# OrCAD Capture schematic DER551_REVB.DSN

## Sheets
1 PAGE1: size Custom; title: DER-551_Inno3X_54W_Dual_USBPD_5V3A_9V3A; rev: B
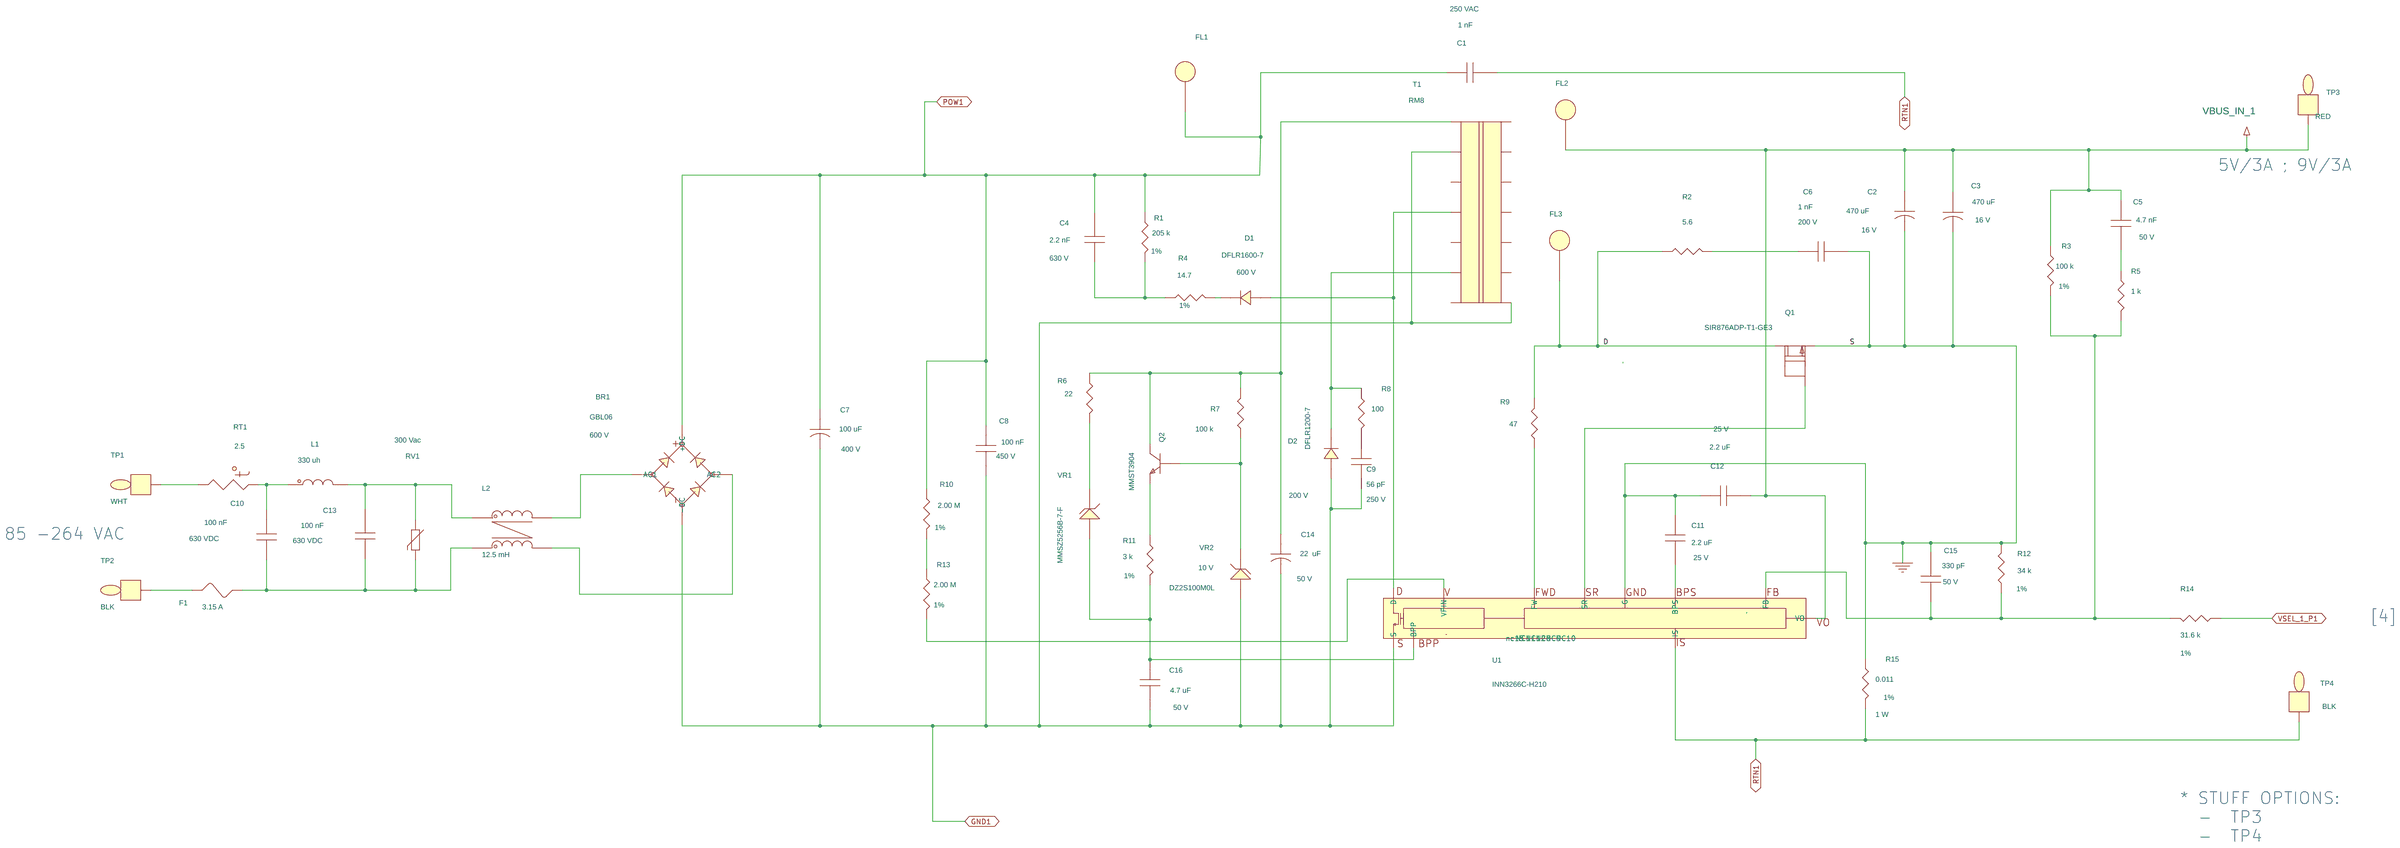
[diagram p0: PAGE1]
2 PAGE2: size Custom
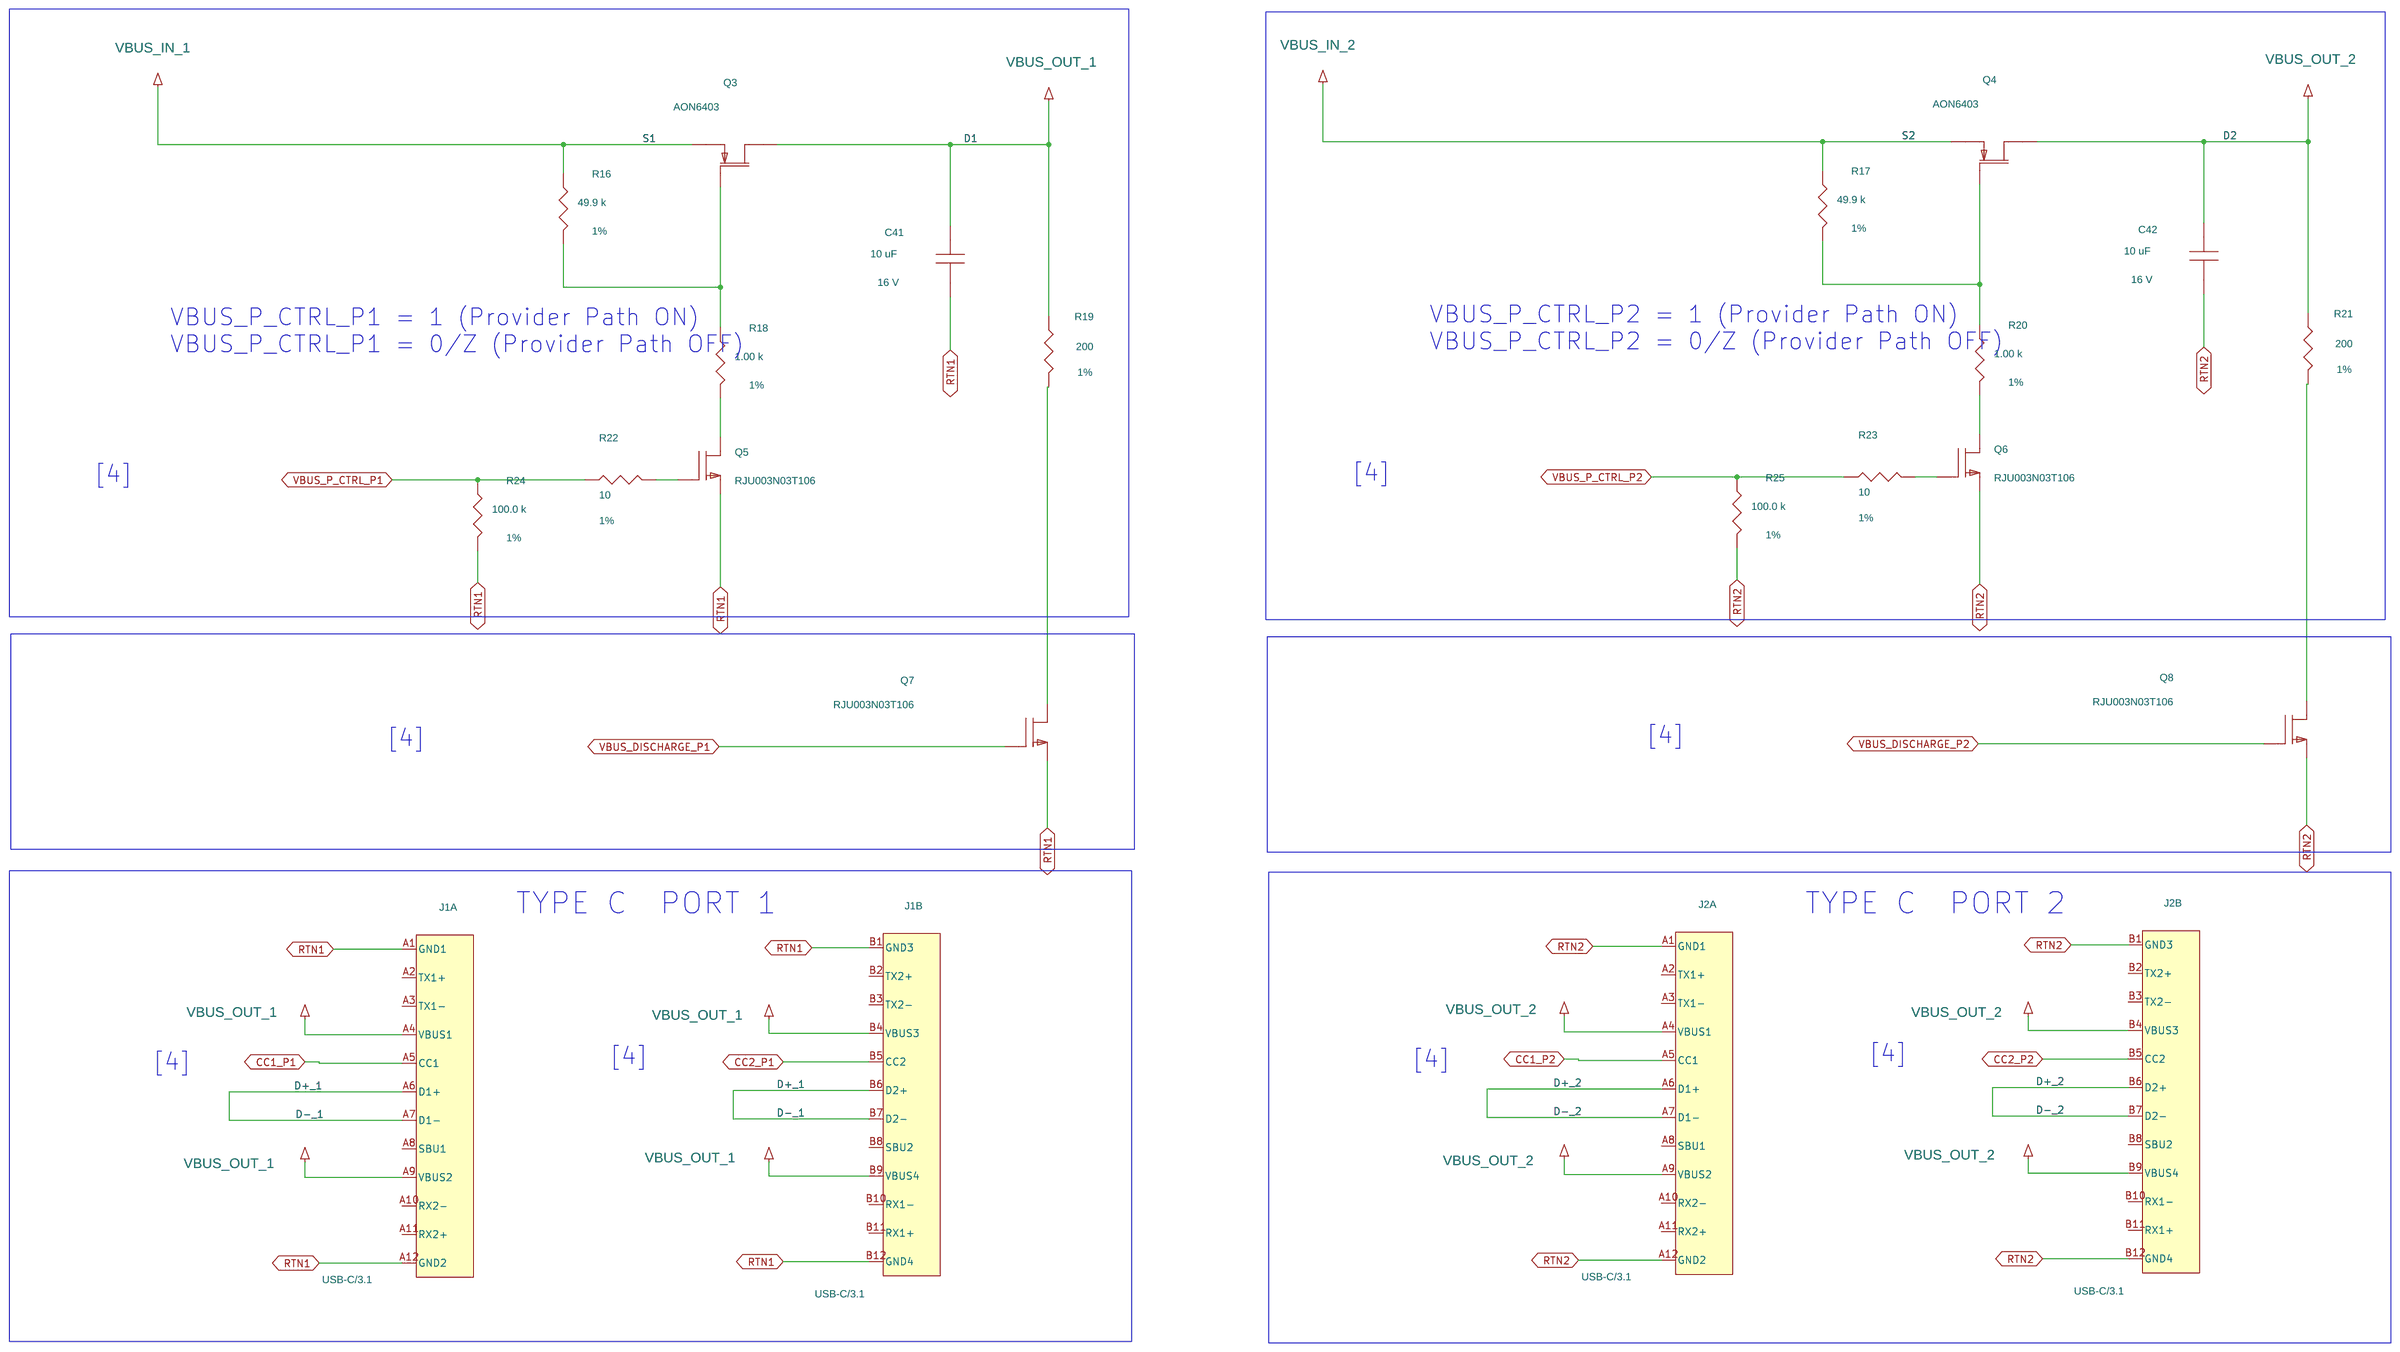
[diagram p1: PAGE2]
3 PAGE3: size Custom
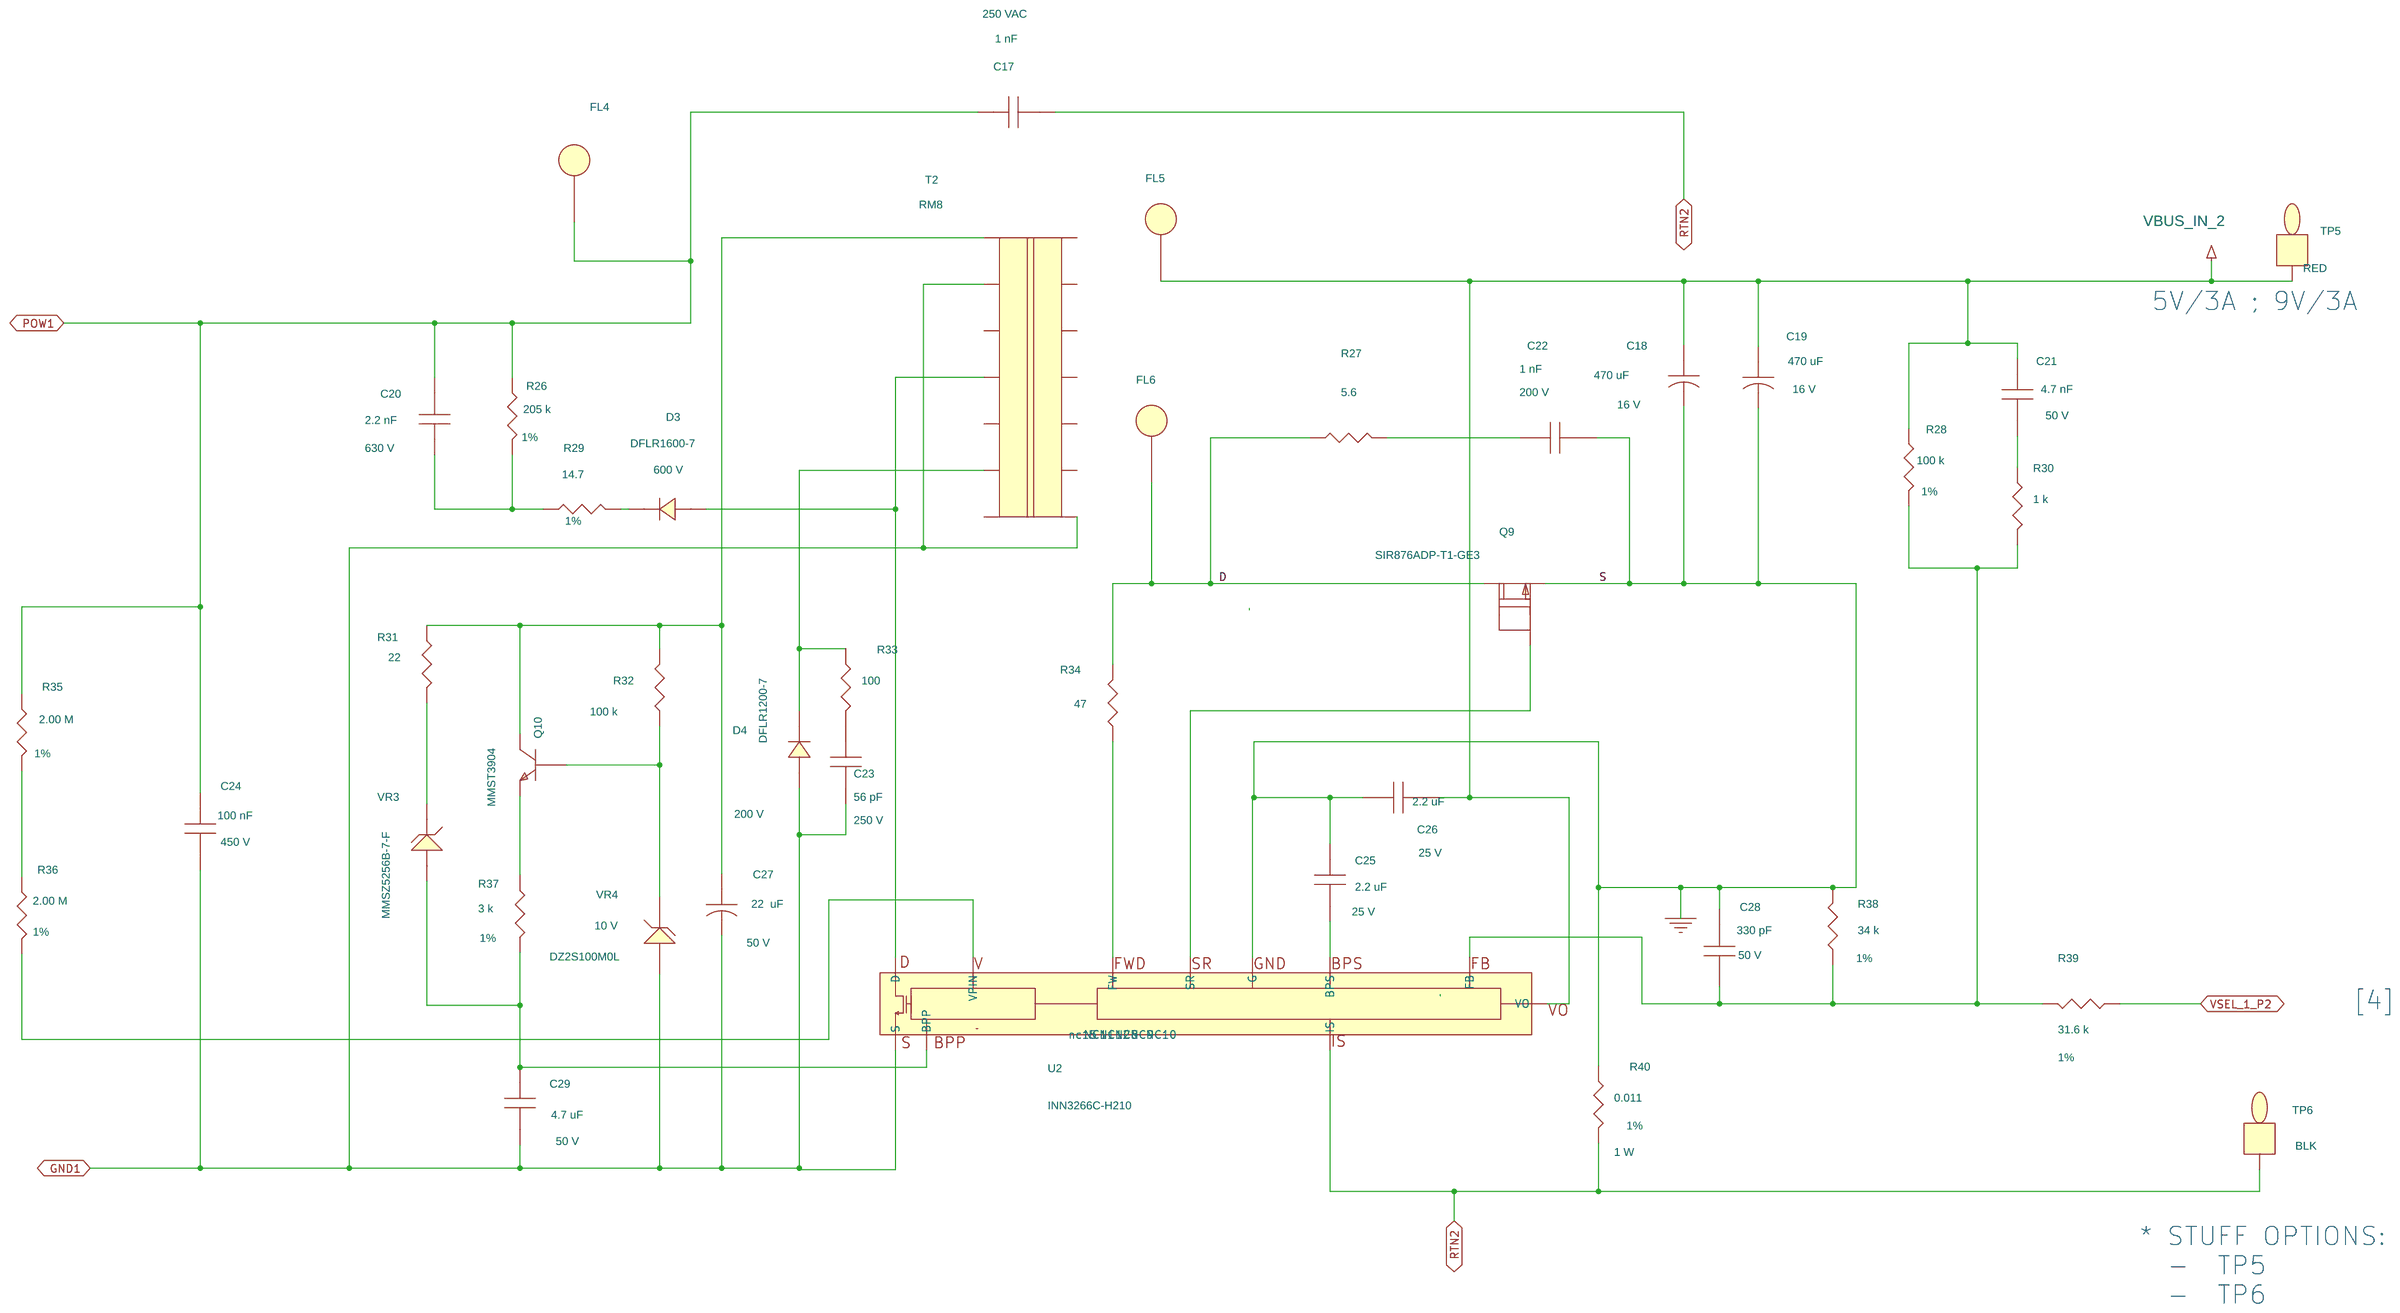
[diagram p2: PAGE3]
4 PAGE4: size Custom
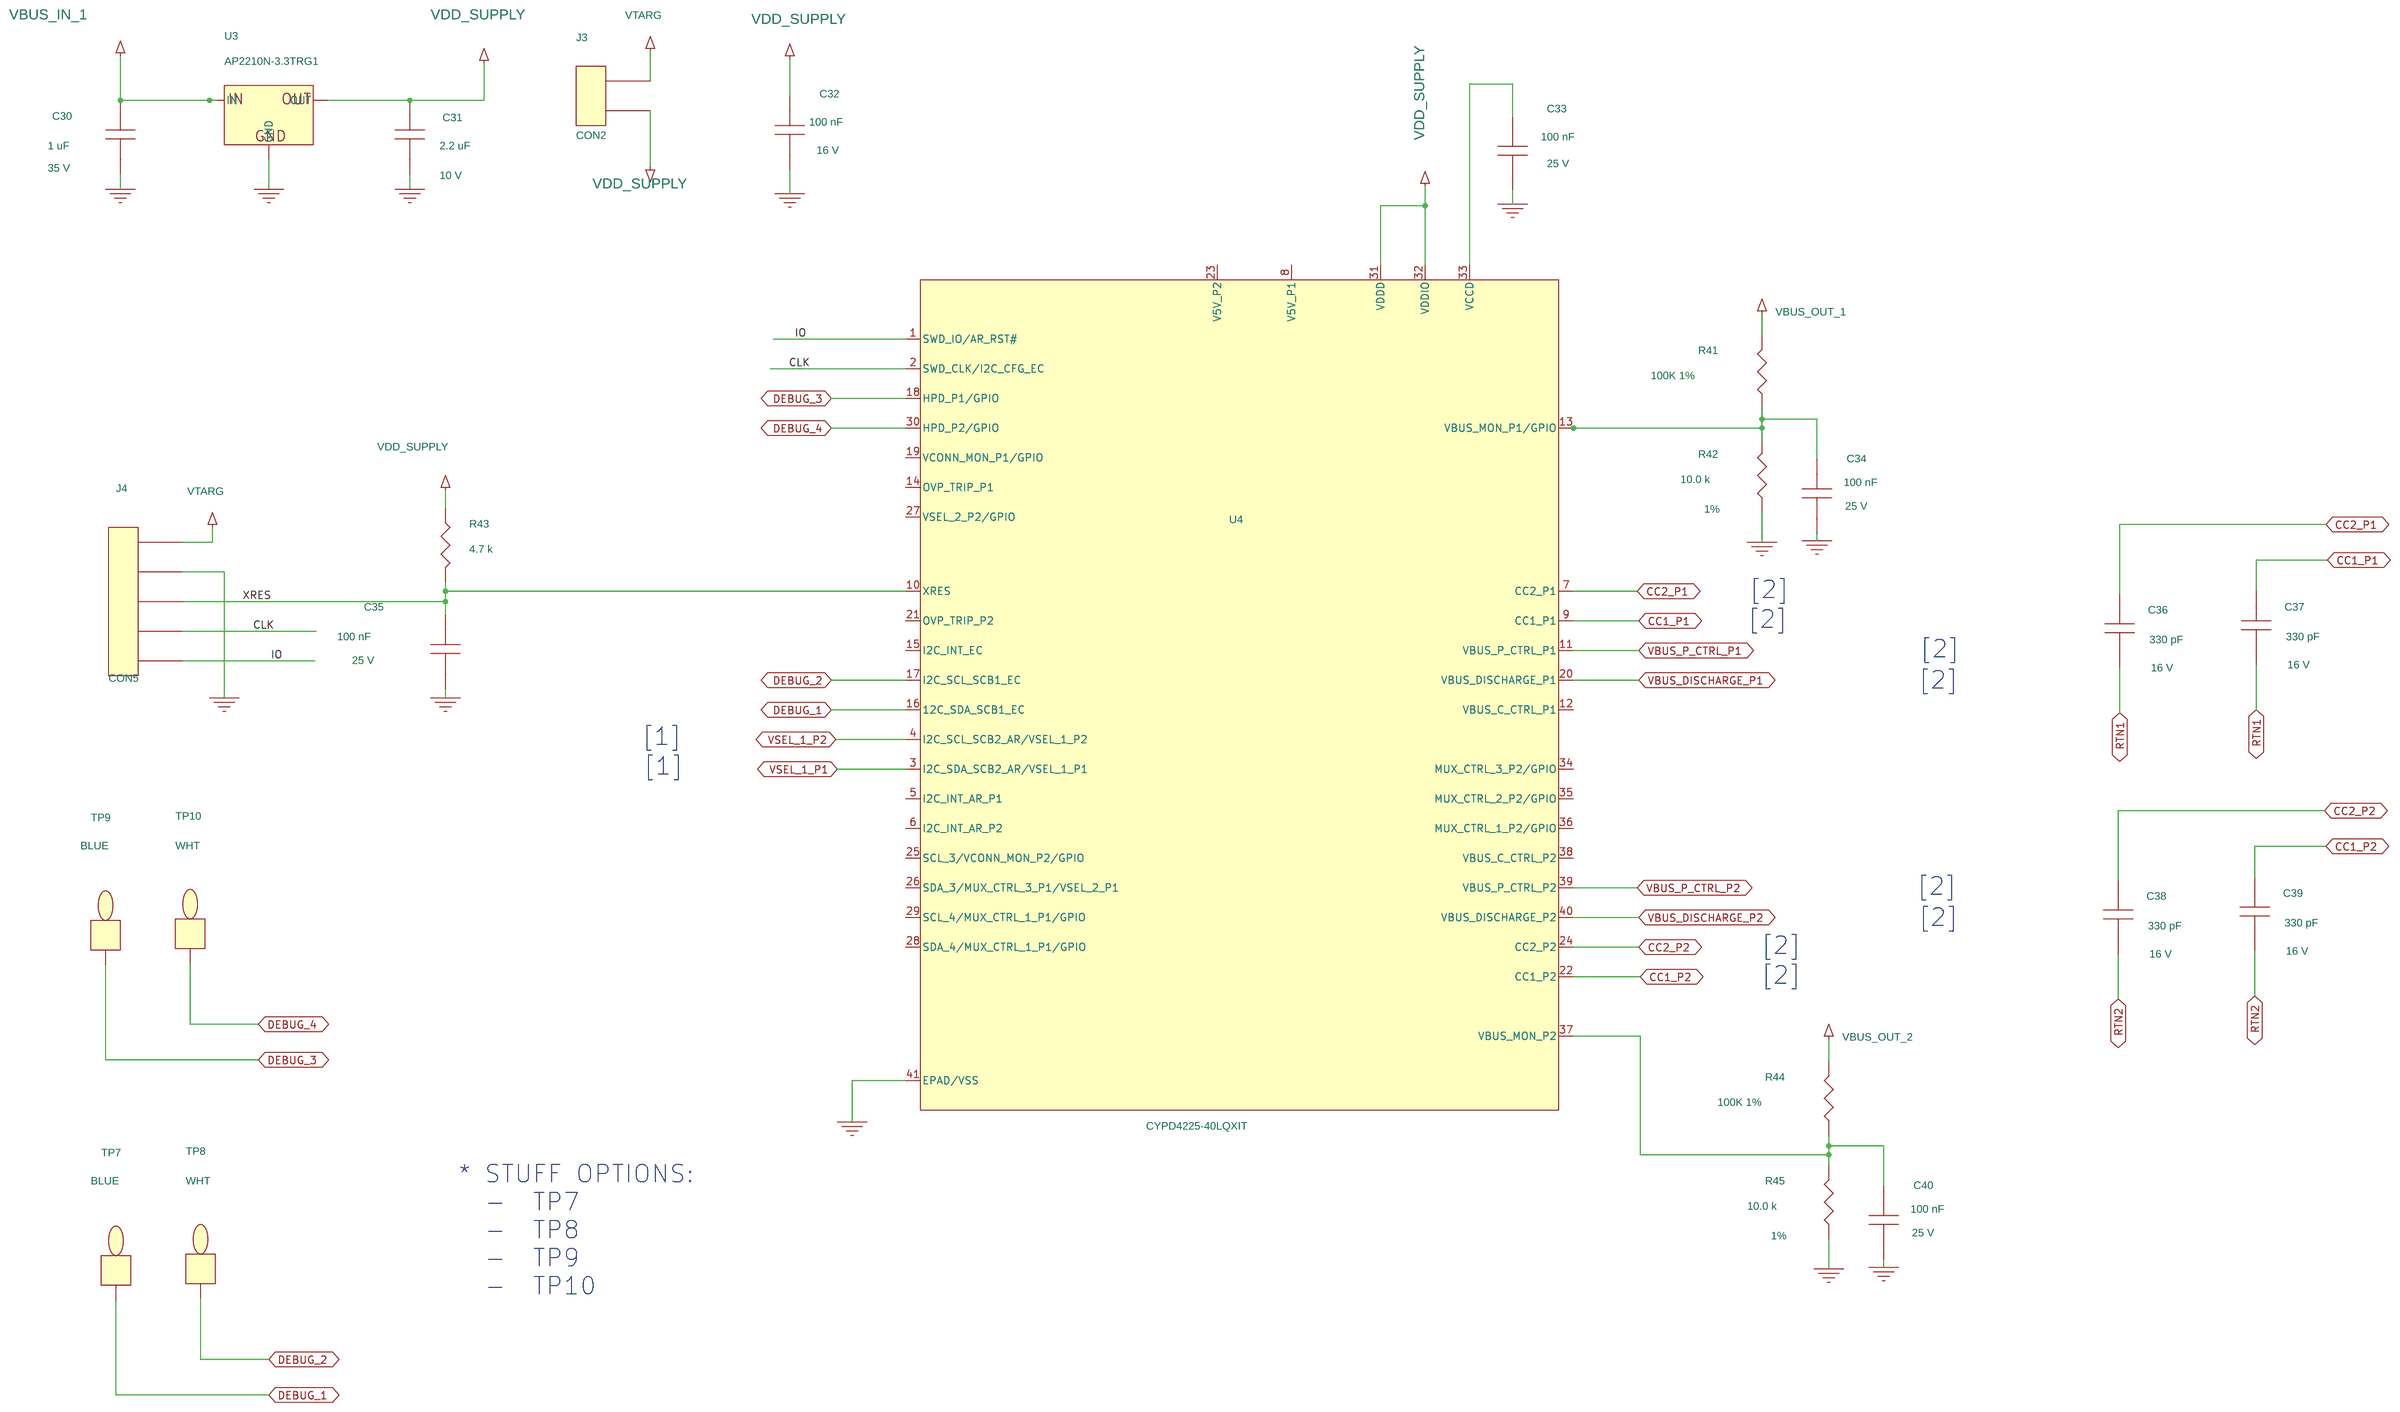
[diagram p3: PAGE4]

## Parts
sheet PAGE1
BR1  GBL06  [pidaxbridgegbl06]
C1  1 nF  [pinpycaprad540x290ls400040]
C2  470 uF  [pipolcapclyd320ls140030]
C3  470 uF  [pipolcapclyd320ls140030]
C4  2.2 nF  [pismc1206]
C5  4.7 nF  [pismc0603]
C6  1 nF  [pismc0805]
C7  100 uF  [pipolcapclyd630ls300040]
C8  100 nF  [pi_np_xcap_rad512x197x395d040]
C9  56 pF  [pismc0603]
C10  100 nF  [pi_np_cap492x236ls394d040]
C11  2.2 uF  [pismc0805]
C12  2.2 uF  [pismc0805]
C13  100 nF  [pi_np_cap492x236ls394d040]
C14  22  uF  [pipolcapclyd200ls80030]
C15  330 pF  [pismc0603]
C16  4.7 uF  [pismc0805]
D1  DFLR1600-7  [pismddflr120012]
D2  DFLR1200-7  [pismddflr120012]
F1  3.15 A  [pi_rst_microfuse]
FL1  Hole_30mils  [pi_hole_30mil]
FL2  Hole_70mils  [pi_hole_70mil]
FL3  Hole_70mils  [pi_hole_70mil]
L1  330 uh  [pi_choke_RL5480-4_d2]
L2  12.5 mH  [PI_TOROID_CMC23X10P7_4P_V]
Q1  SIR876ADP-T1-GE3  [pismpqfn5x6b]
Q2  MMST3904  [pismsot323132]
R1  205 k  [pismr1206]
R2  5.6  [pismr0805]
R3  100 k  [pismr0603]
R4  14.7  [pismr1206]
R5  1 k  [pismr0603]
R6  22  [pismr0603]
R7  100 k  [pismr0603]
R8  100  [pismr0603]
R9  47  [pismr0603]
R10  2.00 M  [pismr1206]
R11  3 k  [pismr0603]
R12  34 k  [pismr0603]
R13  2.00 M  [pismr1206]
R14  31.6 k  [pismr1206]
R15  0.011  [pismr1206]
RT1  2.5  [pi_rad180x395ls235d031]
RV1  300 Vac  [pidisc350x225ls240x140040]
T1  RM8  [pi_bobbin_rm8_12p_clp]
TP1  WHT  [pitpkeystone125x125]
TP2  BLK  [pitpkeystone125x125]
TP3  RED  [pitpkeystone100x100]
TP4  BLK  [pitpkeystone100x100]
U1  INN3266C-H210  [pi_ic_insop_24d]
VR1  MMSZ5256B-7-F  [pi_sm_sod-123_12]
VR2  DZ2S100M0L  [pi_sm_d_ssmini2p]
sheet PAGE2
C41  10 uF  [pismc0805]
C42  10 uF  [pismc0805]
J1  USB-C/3.1  [pi_conn_usb_3p1_top]  (sections A,B)
J2  USB-C/3.1  [pi_conn_usb_3p1_top]  (sections A,B)
Q3  AON6403  [pi_DFN5X6_8L_EP1_P]
Q4  AON6403  [pi_DFN5X6_8L_EP1_P]
Q5  RJU003N03T106  [pismsot323]
Q6  RJU003N03T106  [pismsot323]
Q7  RJU003N03T106  [pismsot323]
Q8  RJU003N03T106  [pismsot323]
R16  49.9 k  [pismr0402]
R17  49.9 k  [pismr0402]
R18  1.00 k  [pismr0805]
R19  200  [pismr1206]
R20  1.00 k  [pismr0805]
R21  200  [pismr1206]
R22  10  [pismr0402]
R23  10  [pismr0402]
R24  100.0 k  [pismr0402]
R25  100.0 k  [pismr0402]
sheet PAGE3
C17  1 nF  [pinpycaprad540x290ls400040]
C18  470 uF  [pipolcapclyd320ls140030]
C19  470 uF  [pipolcapclyd320ls140030]
C20  2.2 nF  [pismc1206]
C21  4.7 nF  [pismc0603]
C22  1 nF  [pismc0805]
C23  56 pF  [pismc0603]
C24  100 nF  [pi_np_xcap_rad512x197x395d040]
C25  2.2 uF  [pismc0805]
C26  2.2 uF  [pismc0805]
C27  22  uF  [pipolcapclyd200ls80030]
C28  330 pF  [pismc0603]
C29  4.7 uF  [pismc0805]
D3  DFLR1600-7  [pismddflr120012]
D4  DFLR1200-7  [pismddflr120012]
FL4  Hole_30mils  [pi_hole_30mil]
FL5  Hole_70mils  [pi_hole_70mil]
FL6  Hole_70mils  [pi_hole_70mil]
Q9  SIR876ADP-T1-GE3  [pismpqfn5x6b]
Q10  MMST3904  [pismsot323132]
R26  205 k  [pismr1206]
R27  5.6  [pismr0805]
R28  100 k  [pismr0603]
R29  14.7  [pismr1206]
R30  1 k  [pismr0603]
R31  22  [pismr0603]
R32  100 k  [pismr0603]
R33  100  [pismr0603]
R34  47  [pismr0603]
R35  2.00 M  [pismr1206]
R36  2.00 M  [pismr1206]
R37  3 k  [pismr0603]
R38  34 k  [pismr0603]
R39  31.6 k  [pismr1206]
R40  0.011  [pismr1206]
T2  RM8  [pi_bobbin_rm8_12p_clp]
TP5  RED  [pitpkeystone100x100]
TP6  BLK  [pitpkeystone100x100]
U2  INN3266C-H210  [pi_ic_insop_24d]
VR3  MMSZ5256B-7-F  [pi_sm_sod-123_12]
VR4  DZ2S100M0L  [pi_sm_d_ssmini2p]
sheet PAGE4
C30  1 uF  [pismc0603]
C31  2.2 uF  [pismc0603]
C32  100 nF  [pismr0402]
C33  100 nF  [pismc0603]
C34  100 nF  [pismc0603]
C35  100 nF  [pismc0603]
C36  330 pF  [pismr0402]
C37  330 pF  [pismr0402]
C38  330 pF  [pismr0402]
C39  330 pF  [pismr0402]
C40  100 nF  [pismc0603]
J3  CON2  [pimolex2kkheader]
J4  CON5  [pi_molex_5p_100_header_ra]
R41  100K 1%  [pismr0402]
R42  10.0 k  [pismr0402]
R43  4.7 k  [pismr0402]
R44  100K 1%  [pismr0402]
R45  10.0 k  [pismr0402]
TP7  BLUE  [pitpkeystone100x100]
TP8  WHT  [pitpkeystone100x100]
TP9  BLUE  [pitpkeystone100x100]
TP10  WHT  [pitpkeystone100x100]
U3  AP2210N-3.3TRG1  [pismsot23132]
U4  CYPD4225-40LQXIT  [qfn50p600x600x60-41t470x470n]

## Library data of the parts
BR1 = DISCRETE_BRIDGE_+~~-: Disp_Voltage: 600 V; Part Number: 15-01112-00
C1 C17 = CAP_NP: ALT_SYMBOLS: pinpycaprad540x290ls400040h,pinpycaprad500x220ls400040; Disp_Voltage: 250 VAC; FPLIST: pinpycaprad540x290ls400040,pinpycaprad540x290ls400040h,pinpycaprad500x220ls400040; Part Number: 20-00375-00; Voltage: 250 VAC
C2 C3 C18 C19 = CAP_POL: ALT_SYMBOLS: pipolcapclyd320ls140030430h; Disp_Voltage: 16 V; FPLIST: pipolcapclyd320ls140030,pipolcapclyd320ls140030430h; Part Number: 20-08681-00; Voltage: 16 V
C4 C20 = CAP_NP: Disp_Voltage: 630 V; Part Number: 20-08609-00; Voltage: 630 V
C5 C21 = CAP_NP: Disp_Voltage: 50 V; Part Number: 20-08578-00; Voltage: 50 V
C6 C22 = CAP_NP: Disp_Voltage: 200 V; PCB Editor PCBFP: pismc0603; Part Number: 20-00737-00; Voltage: 200 V
C7 = CAP_POL: ALT_SYMBOLS: pipolcapclyd630ls3000401120h; Disp_Voltage: 400 V; FPLIST: pipolcapclyd630ls300040,pipolcapclyd630ls3000401120h; Part Number: 20-00517-00; Voltage: 400 V
C8 C24 = CAP_NP: Disp_Voltage: 450 V; Part Number: 20-01140-00; Voltage: 450 V
C9 C23 = CAP_NP: Disp_Voltage: 250 V; Part Number: 20-01325-00; Voltage: 250 V
C10 C13 = CAP_NP: Disp_Voltage: 630 VDC; Part Number: 20-02095-00; Voltage: 630 VDC
C11 C12 C25 C26 = CAP_NP: Disp_Voltage: 25 V; Part Number: 20-08603-00; Voltage: 25 V
C14 C27 = CAP_POL: ALT_SYMBOLS: pipolcapclyd200ls80030h; Disp_Voltage: 50 V; FPLIST: pipolcapclyd200ls80030,pipolcapclyd200ls80030h; Part Number: 20-00950-00; Voltage: 50 V
C15 C28 = CAP_NP: Disp_Voltage: 50 V; Part Number: 20-08676-00; Voltage: 50 V
C16 C29 = CAP_NP: Disp_Voltage: 50 V; Part Number: 20-01130-00; Voltage: 50 V
D1 D3 = DIODE: Disp_Voltage: 600 V; Part Number: 15-00826-00
D2 D4 = DIODE: COMPGROUP: 1; Disp_Voltage: 200 V; Part Number: 15-01019-00
F1 = FUSE: ALT_SYMBOLS: pirstmicrofusehoz; FPLIST: pi_rst_microfuse,pirstmicrofusehoz; Part Number: 40-00020-00
FL1 FL4 = FlyingLead: Part Number: 35-00284-00
FL2 FL3 FL5 FL6 = FlyingLead: Part Number: 35-00282-00
L1 = INDUCTOR_DOT2: ALT_SYMBOLS: pi_choke_RL5480-4H_d2; FPLIST: pi_choke_RL5480-4_d2,pi_choke_RL5480-4H_d2; Part Number: 30-00334-00
L2 = TORRID_4P_14_23: Part Number: 30-00465-00
Q1 Q9 = FET_N_SGD_123_4_5678: Part Number: 50-00152-00
Q2 Q10 = NPN_BEC: Part Number: 55-00016-00
R1 R26 = R: Disp_Tol: 1%; Part Number: 05-00415-00
R2 R27 = R: Part Number: 05-01465-00
R3 R28 = R: Disp_Tol: 1%; Part Number: 05-01174-00
R4 R29 = R: Disp_Tol: 1%; Part Number: 05-00017-00
R5 R30 = R: Part Number: 05-01688-00
R6 R31 = R: Part Number: 05-01648-00
R7 R32 = R: Part Number: 05-01736-00
R8 R33 = R: Part Number: 05-01664-00
R9 R34 = R: Part Number: 05-01656-00
R10 R13 R35 R36 = R: COMPGROUP: 1; Disp_Tol: 1%; Part Number: 05-03156-00
R11 R37 = R: Disp_Tol: 1%; Part Number: 05-06313-00
R12 R38 = R: Disp_Tol: 1%; Part Number: 05-03235-00
R14 R39 = R: Disp_Tol: 1%; Part Number: 05-00337-00
R15 R40 = R: Disp_Power: 1 W; Disp_Tol: 1%; Part Number: 05-06466-00
RT1 = THERMISTOR: ALT_SYMBOLS: pirad550x410ls300040_h; FPLIST: pi_rad180x395ls235d031,pirad550x410ls300040_h; Part Number: 90-00038-00
RV1 = VARISTOR: Part Number: 85-00031-00
T1 T2 = BRM8_12P_CLP: FPLIST: pi_bobbin_rm8_12p_enertronic,pi_bobbin_rm8_12p_clp; Part Number: 25-01084-00
TP1 = TESTPOINT: Part Number: 35-00044-00
TP2 = TESTPOINT: Part Number: 35-00042-00
TP3 TP5 = TESTPOINT: Part Number: 35-00080-00
TP4 TP6 = TESTPOINT: Part Number: 35-00079-00
U1 U2 = Inno3CP: Part Number: 10-01040-04
VR1 VR3 = DIODE_ZENER: Part Number: 15-01096-00
VR2 VR4 = DIODE_ZENER: Disp_Voltage: 10 V; Part Number: 15-00926-00
C41 C42 = CAP_NP: Disp_Voltage: 16 V; Part Number: 20-00676-00; Voltage: 16 V
J1 J2 = CON24_USB: ALT_SYMBOLS: pi_conn_usb_3p1_topD; FPLIST: pi_conn_usb_3p1_top,pi_conn_usb_3p1_topD; Part Number: 35-00354-00
Q3 Q4 = FET_P_SSSGDDDD: Part Number: 50-00209-00
Q5-Q8 = FET_N_SGD: Part Number: 50-00177-00
R16 R17 = R: Disp_Tol: 1%; Part Number: 05-06006-00
R18 R20 = R: Disp_Tol: 1%; Part Number: 05-03310-00
R19 R21 = R: Disp_Tol: 1%; Part Number: 05-00126-00
R22 R23 = R: Disp_Tol: 1%; Part Number: 05-05596-00
R24 R25 = R: Disp_Tol: 1%; Part Number: 05-06039-00
C30 = CAP_NP: Disp_Voltage: 35 V; Part Number: 20-01134-00; Voltage: 35 V
C31 = CAP_NP: Disp_Voltage: 10 V; Part Number: 20-08740-00; Voltage: 10V
C32 = CAP_NP: Disp_Voltage: 16 V; Part Number: 20-08759-00; Voltage: 16 V
C33-C35 C40 = CAP_NP: Disp_Voltage: 25 V; Part Number: 20-01050-00; Voltage: 25 V
C36-C39 = CAP_NP: Disp_Voltage: 16 V; Part Number: 20-08910-00; Voltage: 16 V
J3 = CON2: Part Number: 35-00078-00
J4 = CON5: Part Number: 35-00312-00
R41 R44 = R: RES SMD 100K OHM 1% 1/10W 0402; DIGI-KEY PART NO: P100KLCT-ND; Disp_Tol: 1%; MFG Part number: ERJ-2RKF1003X; Manufacturer: Panasonic Electronic Components; Part Number: 05-06039-00; Price: 0.1
R42 R45 = R: RES SMD 10K OHM 1% 1/10W 0402; DIGI-KEY PART NO: P10.0KLCT-ND; Disp_Tol: 1%; MFG Part number: ERJ-2RKF1002X; Manufacturer: Panasonic Electronic Components; Part Number: 05-05935-00; Price: 0.1
R43 = R: Part Number: 05-06228-00
TP7 TP9 = TESTPOINT: Part Number: 35-00397-00
TP8 TP10 = TESTPOINT: Part Number: 35-00081-00
U3 = AP2210N: Part Number: 45-00352-00
U4 = CYPD4225: Part Number: 45-00451-00

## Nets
GND: C2.2 C3.2 C6.2 C11.1 C12.1 C15.2 C18.2 C19.2 C22.2 C25.1 C26.1 C28.2 C30.2 C31.2 C32.2 C33.2 C34.2 C35.2 C40.2 J4.2 Q1.1(S) Q9.1(S) R12.1 R15.1 R38.1 R40.1 R42.2 R45.2 U1.2(G) U2.2(G) U3.1(GND) U4.41(EPAD/VSS)
GND1: BR1.4(-DC) C7.2 C8.2 C9.2 C14.2 C16.2 C23.2 C24.2 C27.2 C29.2 D2.2 D4.2 T1.2 T1.CLP2 T2.2 T2.CLP2 U1.16(S) U2.16(S) VR2.2 VR4.2
VBUS_DISCHARGE_P1: Q7.2(G) U4.20(VBUS_DISCHARGE_P1)
VBUS_DISCHARGE_P2: Q8.2(G) U4.40(VBUS_DISCHARGE_P2)
VBUS_IN_1: C2.1 C3.1 C5.1 C12.2 C30.1 FL2.1 Q3.1(S1) R3.1 R16.1 TP3.1 U1.6(VO) U3.3(IN)
VBUS_IN_2: C18.1 C19.1 C21.1 C26.2 FL5.1 Q4.1(S1) R17.1 R28.1 TP5.1 U2.6(VO)
VBUS_OUT_1: C41.1 J1.A4(VBUS1) J1.A9(VBUS2) J1.B4(VBUS3) J1.B9(VBUS4) Q3.7(D7) R19.1 R41.1
VBUS_OUT_2: C42.1 J2.A4(VBUS1) J2.A9(VBUS2) J2.B4(VBUS3) J2.B9(VBUS4) Q4.7(D7) R21.1 R44.1
VBUS_P_CTRL_P1: R22.1 R24.1 U4.11(VBUS_P_CTRL_P1)
VBUS_P_CTRL_P2: R23.1 R25.1 U4.39(VBUS_P_CTRL_P2)
VDD_SUPPLY: C31.1 C32.1 J3.1 R43.1 U3.2(OUT) U4.31(VDDD) U4.32(VDDIO)
CC1_P1: C37.1 J1.A5(CC1) U4.9(CC1_P1)
CC1_P2: C39.1 J2.A5(CC1) U4.22(CC1_P2)
CC2_P1: C36.1 J1.B5(CC2) U4.7(CC2_P1)
CC2_P2: C38.1 J2.B5(CC2) U4.24(CC2_P2)
CLK: J4.4 U4.2(SWD_CLK/I2C_CFG_EC)
D: FL3.1 Q1.5(D) R2.2 R9.1
D (page PAGE3): FL6.1 Q9.5(D) R27.2 R34.1
D+_1: J1.A6(D1+) J1.A7(D1-) J1.B6(D2+) J1.B7(D2-)
D+_2: J2.A6(D1+) J2.A7(D1-) J2.B6(D2+) J2.B7(D2-)
DEBUG_1: TP7.1 U4.16(12C_SDA_SCB1_EC)
DEBUG_2: TP8.1 U4.17(I2C_SCL_SCB1_EC)
DEBUG_3: TP9.1 U4.18(HPD_P1/GPIO)
DEBUG_4: TP10.1 U4.30(HPD_P2/GPIO)
IO: J4.5 U4.1(SWD_IO/AR_RST#)
NC8: U1.8(NC8) U2.8(NC8)
NC9: U1.9(NC9) U2.9(NC9)
NC10: U1.10(NC10) U2.10(NC10)
NC11: U1.11(NC11) U2.11(NC11)
NC12: U1.12(NC12) U2.12(NC12)
NC15: U1.15(nc15) U2.15(nc15)
POW1: BR1.1(+DC) C1.1 C4.2 C7.1 C8.1 C17.1 C20.2 C24.1 FL1.1 FL4.1 R1.2 R10.2 R26.2 R35.2
RTN1: C1.2 C36.2 C37.2 C41.2 J1.A1(GND1) J1.A12(GND2) J1.B1(GND3) J1.B12(GND4) Q5.1(S) Q7.1(S) R15.2 R24.2 TP4.1 U1.1(IS)
RTN2: C17.2 C38.2 C39.2 C42.2 J2.A1(GND1) J2.A12(GND2) J2.B1(GND3) J2.B12(GND4) Q6.1(S) Q8.1(S) R25.2 R40.2 TP6.1 U2.1(IS)
VSEL_1_P1: R14.1 U4.3(I2C_SDA_SCB2_AR/VSEL_1_P1)
VSEL_1_P2: R39.1 U4.4(I2C_SCL_SCB2_AR/VSEL_1_P2)
VTARG: J3.2 J4.1
XRES: C35.1 J4.3 R43.2 U4.10(XRES)
N2239928: D1.2 T1.10 U1.24(D)
N2254675: C4.1 R1.1 R4.2
N2276765: C16.1 R11.2 U1.14(BPP) VR1.2
N2494768: C14.1 Q2.3(COLLECTOR) R6.1 R7.1 T1.1
N2642535: Q2.2(EMITTER) R11.1
N2666518: R9.2 U1.7(FW)
N2722737: C6.1 R2.1
N2725054: D2.1 R8.1 T1.12
N2729570: Q1.4(G) U1.5(SR)
N2736973: C15.1 R3.2 R5.2 R12.2 R14.2 U1.3(FB)
N2741729: D1.1 R4.1
N2742169: Q2.1(BASE) R7.2 VR2.1
N2993205: R6.2 VR1.1
N2996861: C5.2 R5.1
N4181205: R10.1 R13.2
N4181233: R13.1 U1.13(VPIN)
N11315036: Q4.4(G) R17.2 R20.1
N11315198: Q6.3(D) R20.2
N11315244: Q8.3(D) R21.2
N11315300: Q6.2(G) R23.2
N11318075: Q3.4(G) R16.2 R18.1
N11318137: Q7.3(D) R19.2
N11318145: Q5.3(D) R18.2
N11318201: Q5.2(G) R22.2
N11323189: C27.1 Q10.3(COLLECTOR) R31.1 R32.1 T2.1
N11323399: D3.2 T2.10 U2.24(D)
N11323505: C22.1 R27.1
N11323517: C21.2 R30.1
N11323551: C20.1 R26.1 R29.2
N11323577: D4.1 R33.1 T2.12
N11323649: D3.1 R29.1
N11323661: C28.1 R28.2 R30.2 R38.2 R39.2 U2.3(FB)
N11323821: Q9.4(G) U2.5(SR)
N11323873: R31.2 VR3.1
N11323885: Q10.1(BASE) R32.2 VR4.1
N11323925: R34.2 U2.7(FW)
N11323959: Q10.2(EMITTER) R37.1
N11324073: C29.1 R37.2 U2.14(BPP) VR3.2
N11324349: R36.1 U2.13(VPIN)
N11338172: R35.1 R36.2
N11773410: F1.2 TP2.1
N11773414: RT1.1 TP1.1
N11773458: C10.1 C13.1 F1.1 L2.1 RV1.2
N11773490: C13.2 L1.1 L2.2 RV1.1
N11773520: BR1.3(AC2) L2.4
N11773524: BR1.2(AC1) L2.3
N11791704: C34.1 R41.2 R42.1 U4.13(VBUS_MON_P1/GPIO)
N11792407: C40.1 R44.2 R45.1 U4.37(VBUS_MON_P2)
N11794782: C33.1 U4.33(VCCD)
N11800517: C10.2 L1.2 RT1.2
N11809700: C11.2 U1.4(BPS)
N11811366: C25.2 U2.4(BPS)
N11812707: C23.1 R33.2
N11857827: C9.1 R8.2

Not connected (* = marked no-connect by the designer): J1 A2(TX1+) A3(TX1-) A8(SBU1) A10(RX2-) A11(RX2+) B2(TX2+) B3(TX2-) B8(SBU2) B10(RX1-) B11(RX1+); J2 A2(TX1+) A3(TX1-) A8(SBU1) A10(RX2-) A11(RX2+) B2(TX2+) B3(TX2-) B8(SBU2) B10(RX1-) B11(RX1+); Q1 2(S2) 3(S3) 6(D6) 7(D7) 8(D8); Q9 2(S2) 3(S3) 6(D6) 7(D7) 8(D8); T1 3 4 5 6 7 8 9 11 CLP1; T2 3 4 5 6 7 8 9 11 CLP1; U4 5(I2C_INT_AR_P1) 6(I2C_INT_AR_P2) 8(V5V_P1) 12(VBUS_C_CTRL_P1) 14(OVP_TRIP_P1) 15(I2C_INT_EC) 19(VCONN_MON_P1/GPIO) 21(OVP_TRIP_P2) 23(V5V_P2) 25(SCL_3/VCONN_MON_P2/GPIO) 26(SDA_3/MUX_CTRL_3_P1/VSEL_2_P1) 27(VSEL_2_P2/GPIO) 28(SDA_4/MUX_CTRL_1_P1/GPIO) 29(SCL_4/MUX_CTRL_1_P1/GPIO) 34(MUX_CTRL_3_P2/GPIO) 35(MUX_CTRL_2_P2/GPIO) 36(MUX_CTRL_1_P2/GPIO) 38(VBUS_C_CTRL_P2)

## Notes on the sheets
sheet 1
- 5V/3A ; 9V/3A
- 85 -264 VAC
- [4]
- * STUFF OPTIONS:
    -  TP3
    -  TP4
sheet 2
- VBUS_P_CTRL_P1 = 1 (Provider Path ON)
  VBUS_P_CTRL_P1 = 0/Z (Provider Path OFF)
- VBUS_P_CTRL_P2 = 1 (Provider Path ON)
  VBUS_P_CTRL_P2 = 0/Z (Provider Path OFF)
- [4]
- [4]
- [4]
- [4]
- TYPE C  PORT 1
- TYPE C  PORT 2
- [4]
- [4]
- [4]
- [4]
sheet 3
- 5V/3A ; 9V/3A
- [4]
- * STUFF OPTIONS:
    -  TP5
    -  TP6
sheet 4
- [2]
- [2]
- [2]
- [2]
- [1]
- [1]
- [2]
- [2]
- [2]
- [2]
- * STUFF OPTIONS:
    -  TP7
    -  TP8
    -  TP9
    -  TP10
